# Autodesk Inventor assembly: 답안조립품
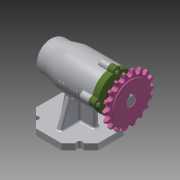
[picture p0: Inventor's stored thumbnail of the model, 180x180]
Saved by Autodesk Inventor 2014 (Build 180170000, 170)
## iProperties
Created: 2021-01
Part Number: 답안조립품
Document SubType Name: Assembly
Designer: kh
Author: kh
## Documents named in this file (12)
- C:\Users\kh\Desktop\710106V1020\답안조립품.iam
- C:\Users\kh\Desktop\710106V1020\본체.ipt
- C:\Users\kh\Desktop\710106V1020\멈춤나사 M3.ipt
- C:\Users\kh\Desktop\710106V1020\베어링 6004.ipt
- C:\Users\kh\Desktop\710106V1020\베어링 51202.ipt
- C:\Users\kh\Desktop\710106V1020\볼트 M4.ipt
- C:\Users\kh\Desktop\710106V1020\스프로킷.ipt
- C:\Users\kh\Desktop\710106V1020\어댑터슬리브.ipt
- C:\Users\kh\Desktop\710106V1020\오일 실.ipt
- C:\Users\kh\Desktop\710106V1020\축.ipt
- C:\Users\kh\Desktop\710106V1020\커버.ipt
- C:\Users\kh\Desktop\710106V1020\키 5 x 5 x 14.ipt
